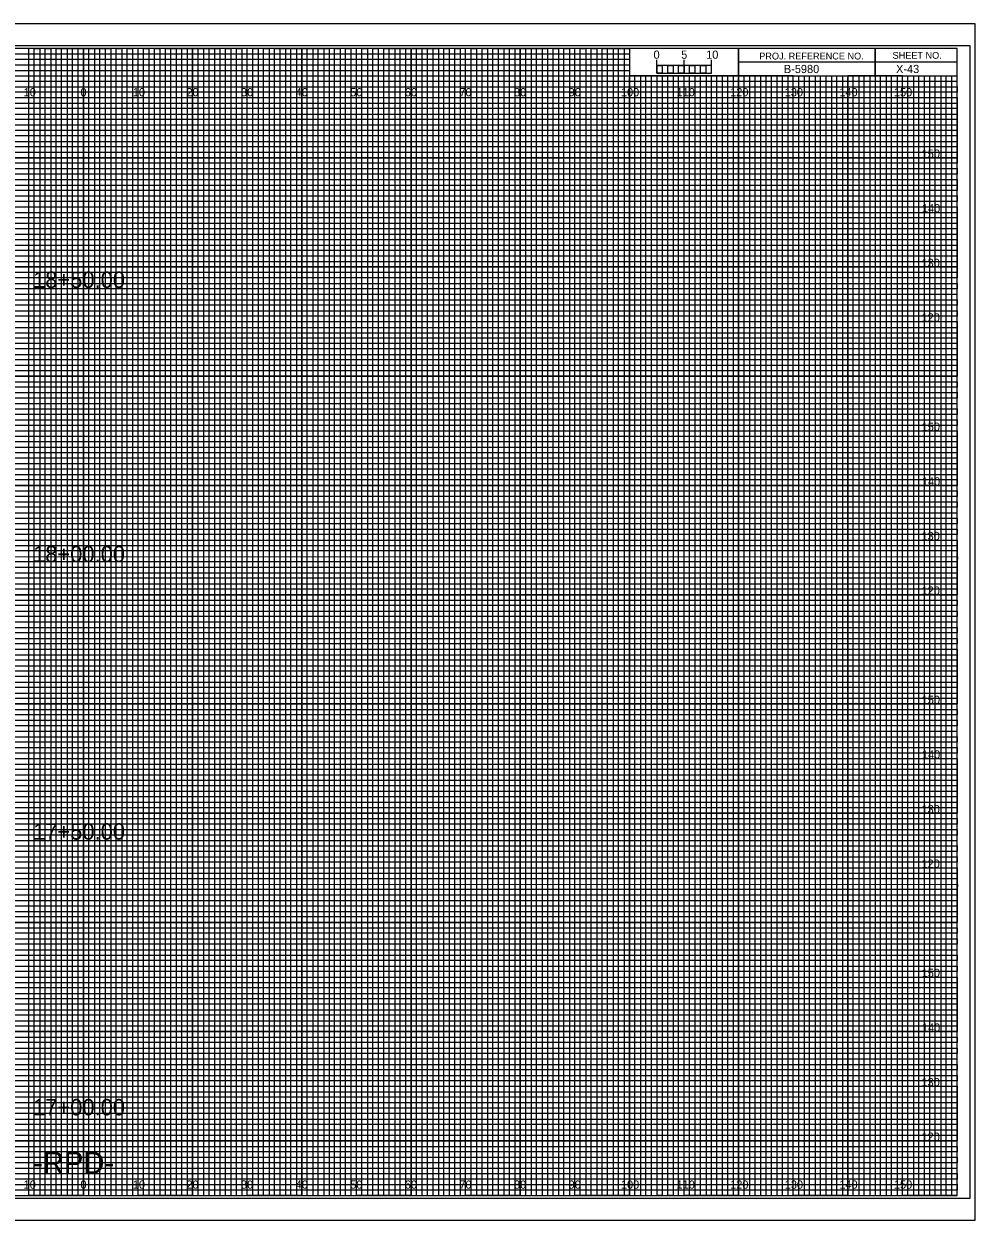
# Model space of a CAD drawing. Extents: x -13 to 323, y -5 to 874.
# Drawn here: x 149.1 to 323.3, y 215.5 to 434.5 of the extents above; entities that cross this region are included whole.
import ezdxf

# ---------------------------------------------------------------- set-up
doc = ezdxf.new("R2010")
doc.units = 0
for name, color, linetype in [('Exist Cross Section Cell', 7, 'Continuous'), ('Exist XS Center Line Elevation Label', 7, 'Continuous'), ('Exist XS Ground Line', 7, 'Continuous'), ('Prop CMT Conc Surface', 7, 'Continuous'), ('Prop CMT Concrete Structures', 7, 'Continuous'), ('Prop CMT Pvmt Course 1', 7, 'Continuous'), ('Prop CMT Pvmt Course 1 CG', 7, 'Continuous'), ('Prop CMT Pvmt Course 2', 7, 'Continuous'), ('Prop CMT Pvmt Course 3', 7, 'Continuous'), ('Prop CMT Pvmt Surface', 7, 'Continuous'), ('Prop CMT Pvmt Surface Shoulder', 7, 'Continuous'), ('Prop CMT Shld Paved Course 1', 7, 'Continuous'), ('Prop CMT Shld Paved Course 2', 7, 'Continuous'), ('Prop CMT Shld Paved Course 3', 7, 'Continuous'), ('Prop CMT Slope Grass', 7, 'Continuous'), ('Prop CMT Subgrade Earthwork', 7, 'Continuous'), ('Scratch_Level_1', 7, 'Continuous')]:
    doc.layers.add(name, color=color, linetype=linetype)

msp = doc.modelspace()

# ---------------------------------------------------------------- linework, layer by layer
at = {"layer": 'Exist XS Center Line Elevation Label'}
for points in [[(145, 220), (155, 220), (155, 430), (165, 430), (165, 220), (175, 220), (175, 430), (185, 430), (185, 220), (195, 220), (195, 430), (205, 430), (205, 220), (215, 220), (215, 430), (225, 430), (225, 220), (235, 220), (235, 430), (245, 430), (245, 220), (255, 220), (255, 430), (259.93, 430), (260, 430), (260, 425), (264.99, 425), (264.99, 220), (275, 220), (275, 425), (285, 425), (285, 220), (295, 220), (295, 425), (305, 425), (305, 220), (315, 220), (315, 425)], [(0, 425), (275, 425)], [(0, 405), (320, 405), (320, 415), (0, 415)], [(0, 385), (320, 385), (320, 395), (0, 395)], [(0, 365), (320, 365), (320, 375), (0, 375)], [(0, 345), (320, 345), (320, 355), (0, 355)], [(0, 325), (320, 325), (320, 335), (0, 335)], [(0, 305), (320, 305), (320, 315), (0, 315)], [(0, 285), (320, 285), (320, 295), (0, 295)], [(0, 265), (320, 265), (320, 275), (0, 275)], [(0, 245), (320, 245), (320, 255), (0, 255)], [(0, 225), (320, 225), (320, 235), (0, 235)]]:
    msp.add_lwpolyline(points, dxfattribs=at)
at = {"layer": 'Exist XS Ground Line'}
for p, q in [((150, 430), (140, 430)), ((150, 220), (150, 430)), ((170, 430), (160, 430)), ((160, 430), (160, 220)), ((170, 220), (170, 430)), ((190, 430), (180, 430)), ((180, 430), (180, 220)), ((190, 220), (190, 430)), ((210, 430), (200, 430)), ((200, 430), (200, 220)), ((210, 220), (210, 430)), ((230, 430), (220, 430)), ((220, 430), (220, 220)), ((230, 220), (230, 430)), ((250, 430), (240, 430)), ((240, 430), (240, 220)), ((250, 220), (250, 430)), ((260, 430), (260, 220)), ((270, 220), (270, 425)), ((290, 425), (280, 425)), ((280, 425), (280, 220)), ((290, 220), (290, 425)), ((310, 425), (300, 425)), ((300, 425), (300, 220)), ((310, 220), (310, 425)), ((160, 220), (150, 220)), ((180, 220), (170, 220)), ((200, 220), (190, 220)), ((220, 220), (210, 220)), ((240, 220), (230, 220)), ((260, 220), (250, 220)), ((280, 220), (270, 220)), ((300, 220), (290, 220)), ((320, 220), (310, 220)), ((320, 220), (320, 220))]:
    msp.add_line(p, q, dxfattribs=at)
for points in [[(0, 420), (320, 420), (320, 410), (0, 410)], [(0, 400), (320, 400), (320, 390), (0, 390)], [(0, 380), (320, 380), (320, 370), (0, 370)], [(0, 360), (320, 360), (320, 350), (0, 350)], [(0, 340), (320, 340), (320, 330), (0, 330)], [(0, 320), (320, 320), (320, 310), (0, 310)], [(0, 300), (320, 300), (320, 290), (0, 290)], [(0, 280), (320, 280), (320, 270), (0, 270)], [(0, 260), (320, 260), (320, 250), (0, 250)], [(0, 240), (320, 240), (320, 230), (0, 230)]]:
    msp.add_lwpolyline(points, dxfattribs=at)
at = {"layer": 'Prop CMT Pvmt Course 2'}
for p, q in [((265, 425.49), (265, 427.9)), ((265, 426.9), (265, 427.9)), ((270, 425.49), (270, 427.9)), ((275, 425.49), (275, 427.9)), ((275, 426.9), (275, 427.9))]:
    msp.add_line(p, q, dxfattribs=at)
for points in [[(275, 426.9), (265, 426.9), (265, 425.49), (275, 425.49)], [(265, 426.9), (266, 426.9), (266, 425.49), (265, 425.49)], [(267, 426.9), (268, 426.9), (268, 425.49), (267, 425.49)], [(269, 426.9), (270, 426.9), (270, 425.49), (269, 425.49)], [(271, 426.9), (272, 426.9), (272, 425.49), (271, 425.49)], [(273, 426.9), (274, 426.9), (274, 425.49), (273, 425.49)]]:
    msp.add_lwpolyline(points, close=True, dxfattribs=at)
at = {"layer": 'Prop CMT Pvmt Course 3'}
msp.add_lwpolyline([(-13.4, 215.5), (323.3, 215.5), (323.3, 434.5), (-13.4, 434.5)], close=True, dxfattribs=at)
at = {"layer": 'Prop CMT Pvmt Surface'}
for p, q in [((150, 220), (150, 430)), ((160, 220), (160, 430)), ((170, 220), (170, 430)), ((180, 220), (180, 430)), ((190, 220), (190, 430)), ((200, 220), (200, 430)), ((210, 220), (210, 430)), ((220, 220), (220, 430)), ((230, 220), (230, 430)), ((240, 220), (240, 430)), ((250, 220), (250, 430)), ((260, 220), (260, 424.69)), ((270, 220), (270, 424.69)), ((280, 220), (280, 424.69)), ((290, 220), (290, 424.69)), ((300, 220), (300, 424.69)), ((310, 220), (310, 424.69)), ((0, 420), (320, 420)), ((0, 410), (320, 410)), ((0, 400), (320, 400)), ((0, 390), (320, 390)), ((0, 380), (320, 380)), ((0, 370), (320, 370)), ((0, 360), (320, 360)), ((0, 350), (320, 350)), ((0, 340), (320, 340)), ((0, 330), (320, 330)), ((0, 320), (320, 320)), ((0, 310), (320, 310)), ((0, 300), (320, 300)), ((0, 290), (320, 290)), ((0, 280), (320, 280)), ((0, 270), (320, 270)), ((0, 260), (320, 260)), ((0, 250), (320, 250)), ((0, 240), (320, 240)), ((0, 230), (320, 230))]:
    msp.add_line(p, q, dxfattribs=at)
at = {"layer": 'Prop CMT Pvmt Surface Shoulder'}
for p, q in [((323.3, 434.5), (-13.4, 434.5)), ((-13.4, 215.5), (323.3, 215.5))]:
    msp.add_line(p, q, dxfattribs=at)
at = {"layer": 'Prop CMT Shld Paved Course 1'}
for p, q in [((0, 429), (260, 429)), ((260, 427.98), (0, 427.98)), ((260, 429), (260, 427.98)), ((0, 427), (260, 427)), ((260, 425.89), (0, 425.89)), ((260, 427), (260, 425.89)), ((0, 424), (320, 424))]:
    msp.add_line(p, q, dxfattribs=at)
for points in [[(0, 423), (270, 423), (320, 423), (320, 422), (0, 422)], [(0, 421), (320, 421), (320, 419), (0, 419)], [(0, 418), (320, 418), (320, 417), (0, 416.98)], [(0, 416), (320, 416), (320, 414), (0, 414)], [(0, 413), (320, 413), (320, 412), (0, 412)], [(0, 411), (320, 411), (320, 409), (0, 409)], [(0, 408), (320, 408), (320, 407), (0, 407)], [(0, 406), (320, 406), (320, 404), (0, 404)], [(0, 403), (320, 403), (320, 402), (0, 402)], [(0, 401), (320, 401), (320, 399), (0, 399)], [(0, 398), (320, 398), (320, 397), (0, 397)], [(0, 396), (320, 396), (320, 393.95), (320, 393), (320, 392), (0, 392)], [(0, 394), (320, 394), (320, 393), (0, 393)], [(0, 391), (320, 391), (320, 389), (0, 389.03)], [(0, 389.03), (320, 389), (320, 388), (0, 388)], [(0, 387), (320, 387), (320, 386), (0, 386)], [(0, 384), (320, 384), (320, 383), (0, 383)], [(0, 382), (320, 382), (320, 381), (0, 381)], [(-0.07, 378.89), (320, 378.89), (320, 377.88), (-0.07, 377.88)], [(0, 377), (320, 377), (320, 376), (0, 376)], [(0, 374), (320, 374), (320, 373), (0, 373)], [(0, 372), (320, 372), (320, 371), (0, 371)], [(0, 369), (320, 369), (320, 368), (0, 368)], [(0, 367), (320, 367), (320, 366), (0, 366)], [(0, 364), (320, 364), (320, 363), (0, 363)], [(0, 362), (320, 362), (320, 361), (0, 361)], [(0, 359), (320, 359), (319.99, 357.98), (0, 358)], [(0, 357), (320, 357), (320, 356), (0, 356)], [(0, 354), (320, 354), (320, 353), (0, 353)], [(0, 352), (320, 352), (320, 351), (0, 351)], [(0, 349), (320, 349), (320, 348), (0, 348)], [(0, 347), (320, 347), (320, 346), (0, 346)], [(0, 344), (320, 344), (320, 343), (0, 343)], [(0, 342), (320, 342), (320, 341), (0, 341)], [(0, 339), (320, 339), (320, 338), (0, 338)], [(0, 336.99), (320.07, 336.91), (320, 336), (0, 336)], [(0, 334), (320, 334), (320, 333), (0, 333)], [(0, 332), (320, 332), (320, 331), (0, 331)], [(0, 329), (320, 329), (320, 328), (0, 328)], [(0, 327), (320, 327), (320, 326), (0, 326)], [(0, 324), (320, 324), (320, 323), (0, 323)], [(0, 322), (320, 322), (320, 321), (0, 321)], [(0, 319), (320, 319), (320, 318), (0, 318)], [(0, 317), (320, 317), (320, 316), (0, 316)], [(0, 314), (320, 314), (320, 313), (0, 313)], [(0, 312), (320, 312), (320, 311), (0, 311)], [(0, 309), (320, 309), (320, 308), (0, 308)], [(0, 307), (320, 307), (320, 306), (0, 306)], [(0, 304), (320, 304), (320, 303), (0, 303)], [(0, 302), (320, 302), (320, 301), (0, 301)], [(0, 299), (320, 299), (319.99, 297.98), (0, 298)], [(0, 297), (320, 297), (320, 296), (0, 296)], [(0, 294), (320, 294), (320, 293), (0, 293)], [(0, 292), (320, 292), (320, 291), (0, 291)], [(0, 289), (320, 289), (320, 288), (0, 288)], [(0, 287), (320, 287), (320, 286), (0, 286)], [(0, 284), (320, 284), (320, 283), (0, 283)], [(0, 282), (320, 282), (320, 281), (0, 281)], [(0, 279), (320, 279), (320, 278), (0, 278)], [(0, 276.99), (320.07, 276.91), (320, 276), (0, 276)], [(0, 274), (320, 274), (320, 273), (0, 273)], [(0, 272), (320, 272), (320, 271), (0, 271)], [(0, 269), (320, 269), (320, 268), (0, 268)], [(0, 267), (320, 267), (320, 266), (0, 266)], [(0, 264), (320, 264), (320, 263), (0, 263)], [(0, 262), (320, 262), (320, 261), (0, 261)], [(0, 259), (320, 259), (320, 258), (0, 258)], [(0, 257), (320, 257), (320, 256), (0, 256)], [(0, 254), (320, 254), (320, 253), (0, 253)], [(0, 252), (320, 252), (320, 251), (0, 251)], [(0, 249), (320, 249), (320, 248), (0, 248)], [(0, 247), (320, 247), (320, 246), (0, 246)], [(0, 244), (320, 244), (320, 243), (0, 243)], [(0, 242), (320, 242), (320, 241), (0, 241)], [(0, 239), (320, 239), (320, 238), (0, 238)], [(0, 237), (320, 237), (320, 236), (0, 236)], [(0, 234), (320, 234), (320, 233), (0, 233)], [(0, 232), (320, 232), (320, 231), (0, 231)], [(0, 229), (320, 229), (320, 228), (0, 228)], [(0, 227), (320, 227), (320, 226), (0, 226)], [(0, 224), (320, 224), (320, 223), (0, 223)], [(0, 222), (320, 222), (320, 221), (0, 221)]]:
    msp.add_lwpolyline(points, dxfattribs=at)
at = {"layer": 'Prop CMT Shld Paved Course 2'}
for p, q in [((305, 430), (305, 425)), ((305, 425), (305, 430)), ((280, 427.5), (280, 425)), ((320, 427.49), (280, 427.49)), ((280, 425), (320, 425))]:
    msp.add_line(p, q, dxfattribs=at)
for points in [[(320, 430), (0, 430), (0, 220), (320, 220)], [(280, 430), (260, 430), (260, 425.03), (280, 425.03)], [(320, 430), (280, 430), (280, 425), (320, 425)]]:
    msp.add_lwpolyline(points, close=True, dxfattribs=at)
at = {"layer": 'Prop CMT Shld Paved Course 3'}
for p, q in [((267, 425), (266.01, 425)), ((266.01, 425), (266.01, 220)), ((267, 220), (267, 425)), ((269, 425), (268, 425)), ((268, 425), (268, 220)), ((269, 220), (269, 425)), ((266.01, 220), (265, 220)), ((268, 220), (267, 220))]:
    msp.add_line(p, q, dxfattribs=at)
for points in [[(150, 220), (151, 220), (151, 430), (152, 430), (152, 220)], [(152, 220), (153, 220), (153, 430), (154, 430), (154, 220)], [(155, 220), (156, 220), (156, 430), (157, 430), (157, 220)], [(157, 220), (158, 220), (158, 430), (159, 430), (159, 220)], [(160, 220), (161, 220), (161, 430), (162, 430), (162, 220)], [(162, 220), (163, 220), (163, 430), (164, 430), (164, 220)], [(165, 220), (166, 220), (166, 430), (167, 430), (167, 220)], [(167, 220), (168, 220), (168, 430), (169, 430), (169, 220)], [(170, 220), (171, 220), (171, 430), (172, 430), (172, 220)], [(172, 220), (173, 220), (173, 430), (174, 430), (174, 220)], [(175, 220), (176, 220), (176, 430), (177, 430), (177, 220)], [(177, 220), (178, 220), (178, 430), (179, 430), (179, 220)], [(180, 220), (181, 220), (181, 430), (182, 430), (182, 220)], [(182, 220), (183, 220), (183, 430), (184, 430), (184, 220)], [(185, 220), (186, 220), (186, 430), (187, 430), (187, 220)], [(187, 220), (188, 220), (188, 430), (189, 430), (189, 220)], [(190, 220), (191, 220), (191, 430), (192, 430), (192, 220)], [(192, 220), (193, 220), (193, 430), (194, 430), (194, 220)], [(195, 220), (196, 220), (196, 430), (197, 430), (197, 220)], [(197, 220), (198, 220), (198, 430), (199, 430), (199, 220)], [(200, 220), (201, 220), (201, 430), (202, 430), (202, 220)], [(202, 220), (203, 220), (203, 430), (204, 430), (204, 220)], [(205, 220), (206, 220), (206, 430), (207, 430), (207, 220)], [(207, 220), (208, 220), (208, 430), (209, 430), (209, 220)], [(210, 220), (211, 220), (211, 430), (212, 430), (212, 220)], [(212, 220), (213, 220), (213, 430), (214, 430), (214, 220)], [(215, 220), (216, 220), (216, 430), (217, 430), (217, 220)], [(217, 220), (218, 220), (218, 430), (219, 430), (219, 220)], [(220, 220), (221, 220), (221, 430), (222, 430), (222, 220)], [(222, 220), (223, 220), (223, 430), (224, 430), (224, 220)], [(225, 220), (226, 220), (226, 430), (227, 430), (227, 220)], [(227, 220), (228, 220), (228, 430), (229, 430), (229, 220)], [(230, 220), (231, 220), (231, 430), (232, 430), (232, 220)], [(232, 220), (233, 220), (233, 430), (234, 430), (234, 220)], [(235, 220), (236, 220), (236, 430), (237, 430), (237, 220)], [(237, 220), (238, 220), (238, 430), (239, 430), (239, 220)], [(240, 220), (241, 220), (241, 430), (242, 430), (242, 220)], [(242, 220), (243, 220), (243, 430), (244, 430), (244, 220)], [(245, 220), (246, 220), (246, 430), (247, 430), (247, 220)], [(247, 220), (248, 220), (248, 430), (249, 430), (249, 220)], [(250, 220), (251, 220), (251, 430), (252, 430), (252, 220)], [(252, 220), (253, 220), (253, 430), (254, 430), (254, 220)], [(255, 220), (256, 220), (256, 430), (257, 430), (257, 220)], [(257, 220), (258, 220), (258, 430), (259, 430), (259, 220)], [(260, 220), (261, 220), (261, 425), (262.02, 425), (262.02, 220)], [(262, 220), (263, 220), (263, 425), (263.99, 425), (263.99, 220)], [(270, 220), (270.98, 220), (270.98, 425), (272, 425), (272, 220)], [(272, 220), (273, 220), (273, 425), (274.05, 425), (274.05, 220)], [(275, 220), (276, 220), (276, 425), (277, 425), (277, 220)], [(277, 220), (278, 220), (278, 425), (279, 425), (279, 220)], [(280, 220), (281, 220), (281, 425), (282, 425), (282, 220)], [(282, 220), (283, 220), (283, 425), (284, 425), (284, 220)], [(285, 220), (286, 220), (286, 425), (287, 425), (287, 220)], [(287, 220), (288, 220), (288, 425), (289, 425), (289, 220)], [(290, 220), (291, 220), (291, 425), (292, 425), (292, 220)], [(292, 220), (293, 220), (293, 425), (294, 425), (294, 220)], [(295, 220), (296, 220), (296, 425), (297, 425), (297, 220)], [(297, 220), (298, 220), (298, 425), (299, 425), (299, 220)], [(300, 220), (301, 220), (301, 425), (302, 425), (302, 220)], [(302, 220), (303, 220), (303, 425), (304, 425), (304, 220)], [(305, 220), (306, 220), (306, 425), (307, 425), (307, 220)], [(307, 220), (308, 220), (308, 425), (309, 425), (309, 220)], [(310, 220), (311, 220), (311, 425), (312, 425), (312, 220)], [(312, 220), (313, 220), (313, 425), (314, 425), (314, 220)], [(315, 220), (316, 220), (316, 425), (317, 425), (317, 220)], [(317, 220), (318, 220), (318, 425), (319, 425), (319, 220)]]:
    msp.add_lwpolyline(points, dxfattribs=at)
at = {"layer": 'Prop CMT Subgrade Earthwork'}
msp.add_lwpolyline([(-10.8, 219.5), (322.4, 219.5), (322.4, 430.5), (-10.8, 430.5)], close=True, dxfattribs=at)

# ---------------------------------------------------------------- texts
at = {"layer": 'Exist Cross Section Cell'}
for s, p in [('10', (149.04, 421.25)), ('0', (159.45, 421.25)), ('0', (159.45, 421.25)), ('10', (169.04, 421.25)), ('20', (178.86, 421.25)), ('30', (188.86, 421.25)), ('40', (198.86, 421.25)), ('50', (208.86, 421.25)), ('60', (218.86, 421.25)), ('70', (228.86, 421.25)), ('80', (238.86, 421.25)), ('90', (248.86, 421.25)), ('100', (258.44, 421.25)), ('110', (268.62, 421.25)), ('120', (278.44, 421.25)), ('130', (288.44, 421.25)), ('140', (298.44, 421.25)), ('150', (308.44, 421.25)), ('10', (149.04, 221.25)), ('0', (159.45, 221.25)), ('0', (159.45, 221.25)), ('10', (169.04, 221.25)), ('20', (178.86, 221.25)), ('30', (188.86, 221.25)), ('40', (198.86, 221.25)), ('50', (208.86, 221.25)), ('60', (218.86, 221.25)), ('70', (228.86, 221.25)), ('80', (238.86, 221.25)), ('90', (248.86, 221.25)), ('100', (258.44, 221.25)), ('110', (268.62, 221.25)), ('120', (278.44, 221.25)), ('130', (288.44, 221.25)), ('140', (298.44, 221.25)), ('150', (308.44, 221.25))]:
    msp.add_text(s, height=1.5, dxfattribs=at).set_placement(p)
at = {"layer": 'Prop CMT Conc Surface'}
for s, p in [('5', (269.47, 428.12)), ('10', (274.04, 428.12))]:
    msp.add_text(s, height=1.5, dxfattribs=at).set_placement(p)
at = {"layer": 'Prop CMT Concrete Structures'}
msp.add_text('B-5980', height=1.5, dxfattribs=at).set_placement((288.28, 425.5))
at = {"layer": 'Prop CMT Pvmt Course 1'}
for s, p in [('150', (313.52, 410)), ('140', (313.57, 400)), ('130', (313.49, 390)), ('120', (313.5, 380)), ('150', (313.52, 360)), ('140', (313.57, 350)), ('130', (313.49, 340)), ('120', (313.5, 330)), ('150', (313.52, 310)), ('140', (313.57, 300)), ('130', (313.49, 290)), ('120', (313.5, 280)), ('150', (313.52, 260)), ('140', (313.57, 250)), ('130', (313.49, 240)), ('120', (313.5, 230))]:
    msp.add_text(s, height=1.5, dxfattribs=at).set_placement(p)
at = {"layer": 'Prop CMT Pvmt Course 1 CG'}
msp.add_text('-RPD-', height=4, dxfattribs=at).set_placement((150.78, 224))
at = {"layer": 'Prop CMT Pvmt Course 2'}
msp.add_text('0', height=1.5, dxfattribs=at).set_placement((264.41, 428.12))
at = {"layer": 'Prop CMT Shld Paved Course 2'}
for s, p in [('PROJ. REFERENCE NO.', (283.77, 427.99)), ('SHEET NO.', (308.19, 428.12))]:
    msp.add_text(s, height=1.25, dxfattribs=at).set_placement(p)
at = {"layer": 'Prop CMT Slope Grass'}
for s, p in [('18+50.00', (150.77, 386.17)), ('18+00.00', (150.77, 335.94)), ('17+50.00', (150.77, 285.15)), ('17+00.00', (150.77, 234.67))]:
    msp.add_text(s, height=3, dxfattribs=at).set_placement(p)
at = {"layer": 'Scratch_Level_1'}
msp.add_text('X-43', height=1.5, dxfattribs=at).set_placement((308.83, 425.5))

doc.saveas('drawing.dxf')
